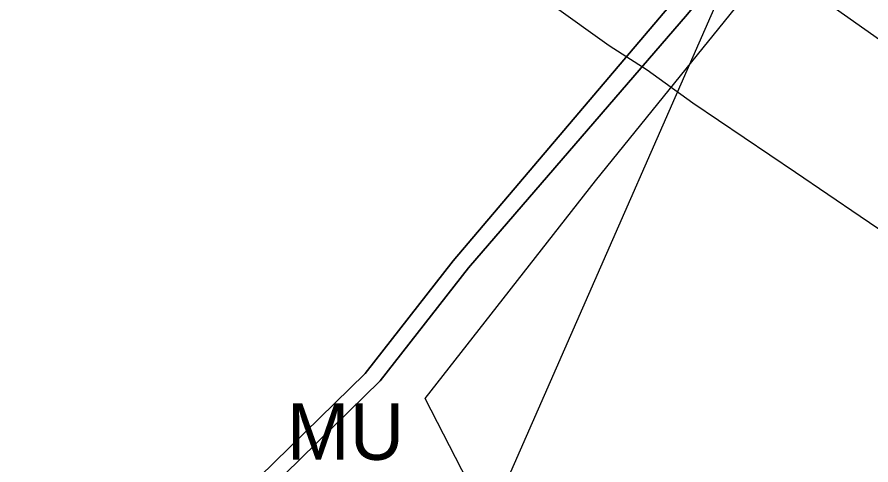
# Model space of a CAD drawing. Extents: x -690419 to -685080, y -987825 to -981190.
# Drawn here: x -688363.8 to -688212.4, y -984240.6 to -984161.1 of the extents above; entities that cross this region are included whole.
import ezdxf

# ---------------------------------------------------------------- set-up
doc = ezdxf.new("R2010")
doc.units = 0
for name, color, linetype in [('BP VTL plynovodu a RS (S)', 7, 'Continuous'), ('Investice do půdy_hlavní odvodňovací zařízení zatrubněné S', 7, 'Continuous'), ('OP lesa 50 m (S)', 7, 'Continuous'), ('Plochy smíšené nezastavěného území všeobecné MU (S)', 7, 'Continuous'), ('Plochy zemědělské všeobecné AU (S)', 7, 'Continuous'), ('Regulační bloky STABILIZOVANÉ (S)', 7, 'Continuous'), ('Regulační kódy STABILIZOVANÉ (S)', 7, 'Continuous'), ('Spoje - MW trasy', 7, 'Continuous')]:
    doc.layers.add(name, color=color, linetype=linetype)

msp = doc.modelspace()

# ---------------------------------------------------------------- linework, layer by layer
at = {"layer": 'BP VTL plynovodu a RS (S)'}
msp.add_lwpolyline([(-688384.84, -984095.06), (-688382.54, -984094.84), (-688374.67, -984093.74), (-688371.64, -984095.5), (-688355.87, -984104.55), (-688339.01, -984114.35), (-688322.19, -984124.8), (-688300.6, -984138.49), (-688289.3, -984145.84), (-688268.98, -984158.93), (-688258.77, -984166.21), (-688252.04, -984170.5), (-688243.95, -984176.38), (-688225.75, -984188.67), (-688214.29, -984196.47), (-688189.99, -984212.96)], dxfattribs=at)
at = {"layer": 'Investice do půdy_hlavní odvodňovací zařízení zatrubněné S'}
msp.add_lwpolyline([(-688287.85, -984494.25), (-688269.99, -984395.46), (-688253.67, -984302.39), (-688291.41, -984228.84), (-688261.25, -984190.21), (-688221.3, -984140.74), (-688188.32, -984136.51)], dxfattribs=at)
at = {"layer": 'OP lesa 50 m (S)'}
msp.add_lwpolyline([(-688370.03, -984072.55), (-688368.75, -984072.71), (-688367.71, -984073.01), (-688327.78, -984084.73), (-688320.67, -984087.58), (-688308.6, -984095.71), (-688237.05, -984146.6), (-688236.9, -984146.71), (-688230.51, -984151.23), (-688193.83, -984177.11)], dxfattribs=at)
at = {"layer": 'Plochy smíšené nezastavěného území všeobecné MU (S)'}
msp.add_lwpolyline([(-688096.34, -984204.36), (-688215.15, -984124.66), (-688244.91, -984160.62), (-688283.72, -984205.64), (-688299.38, -984225.7), (-688319.09, -984245.01), (-688333.33, -984258.62), (-688350.63, -984272.75), (-688434.3, -984350.74), (-688463.41, -984383.11), (-688464.89, -984380.5), (-688444.89, -984358.12), (-688417.17, -984330.26), (-688386.77, -984301.57), (-688352.42, -984270.6), (-688335.25, -984256.31), (-688320.86, -984242.81), (-688302.04, -984224.42), (-688286.45, -984204.39), (-688247.24, -984158.13), (-688221.07, -984121.18), (-688223.2, -984112.33), (-688201.56, -984127.44)], dxfattribs=at)
at = {"layer": 'Plochy zemědělské všeobecné AU (S)'}
for points in [[(-688479.92, -984241.13), (-688451.12, -984212.71), (-688440.98, -984195.15), (-688435.82, -984184.61), (-688426.08, -984164.69), (-688417.78, -984147.72), (-688416.58, -984145.75), (-688415.54, -984144.05), (-688411.77, -984146.33), (-688381.16, -984092.4), (-688360.57, -984063.22), (-688359.16, -984059.76), (-688351.6, -984041.22), (-688360.38, -984037.58), (-688334.64, -984043.24), (-688319.91, -984048.92), (-688305.22, -984056.23), (-688288.11, -984067.01), (-688223.2, -984112.33), (-688221.07, -984121.18), (-688247.24, -984158.13), (-688286.45, -984204.39), (-688302.04, -984224.42), (-688320.86, -984242.81)], [(-688202.14, -984406.52), (-688229.17, -984377.69), (-688244.28, -984361.58), (-688251.93, -984353.43), (-688259.5, -984344.63), (-688267.14, -984335.75), (-688310.66, -984285.19), (-688333.33, -984258.62), (-688319.09, -984245.01), (-688299.38, -984225.7), (-688283.72, -984205.64), (-688244.91, -984160.62), (-688215.15, -984124.66), (-688096.34, -984204.36)]]:
    msp.add_lwpolyline(points, dxfattribs=at)
at = {"layer": 'Regulační bloky STABILIZOVANÉ (S)'}
for points in [[(-688479.92, -984241.13), (-688451.12, -984212.71), (-688440.98, -984195.15), (-688435.82, -984184.61), (-688426.08, -984164.69), (-688417.78, -984147.72), (-688416.58, -984145.75), (-688415.54, -984144.05), (-688411.77, -984146.33), (-688381.16, -984092.4), (-688360.57, -984063.22), (-688359.16, -984059.76), (-688351.6, -984041.22), (-688360.38, -984037.58), (-688334.64, -984043.24), (-688319.91, -984048.92), (-688305.22, -984056.23), (-688288.11, -984067.01), (-688223.2, -984112.33), (-688221.07, -984121.18), (-688247.24, -984158.13), (-688286.45, -984204.39), (-688302.04, -984224.42), (-688320.86, -984242.81)], [(-688096.34, -984204.36), (-688215.15, -984124.66), (-688244.91, -984160.62), (-688283.72, -984205.64), (-688299.38, -984225.7), (-688319.09, -984245.01), (-688333.33, -984258.62), (-688350.63, -984272.75), (-688434.3, -984350.74), (-688463.41, -984383.11), (-688464.89, -984380.5), (-688444.89, -984358.12), (-688417.17, -984330.26), (-688386.77, -984301.57), (-688352.42, -984270.6), (-688335.25, -984256.31), (-688320.86, -984242.81), (-688302.04, -984224.42), (-688286.45, -984204.39), (-688247.24, -984158.13), (-688221.07, -984121.18), (-688223.2, -984112.33), (-688201.56, -984127.44)], [(-688202.14, -984406.52), (-688229.17, -984377.69), (-688244.28, -984361.58), (-688251.93, -984353.43), (-688259.5, -984344.63), (-688267.14, -984335.75), (-688310.66, -984285.19), (-688333.33, -984258.62), (-688319.09, -984245.01), (-688299.38, -984225.7), (-688283.72, -984205.64), (-688244.91, -984160.62), (-688215.15, -984124.66), (-688096.34, -984204.36)]]:
    msp.add_lwpolyline(points, dxfattribs=at)
at = {"layer": 'Spoje - MW trasy'}
msp.add_lwpolyline([(-688164.9, -983987.83), (-688465.48, -984673.28)], dxfattribs=at)

# ---------------------------------------------------------------- texts
at = {"layer": 'Regulační kódy STABILIZOVANÉ (S)'}
msp.add_text('MU', height=10, dxfattribs=at).set_placement((-688315.94, -984239.72))

doc.saveas('drawing.dxf')
